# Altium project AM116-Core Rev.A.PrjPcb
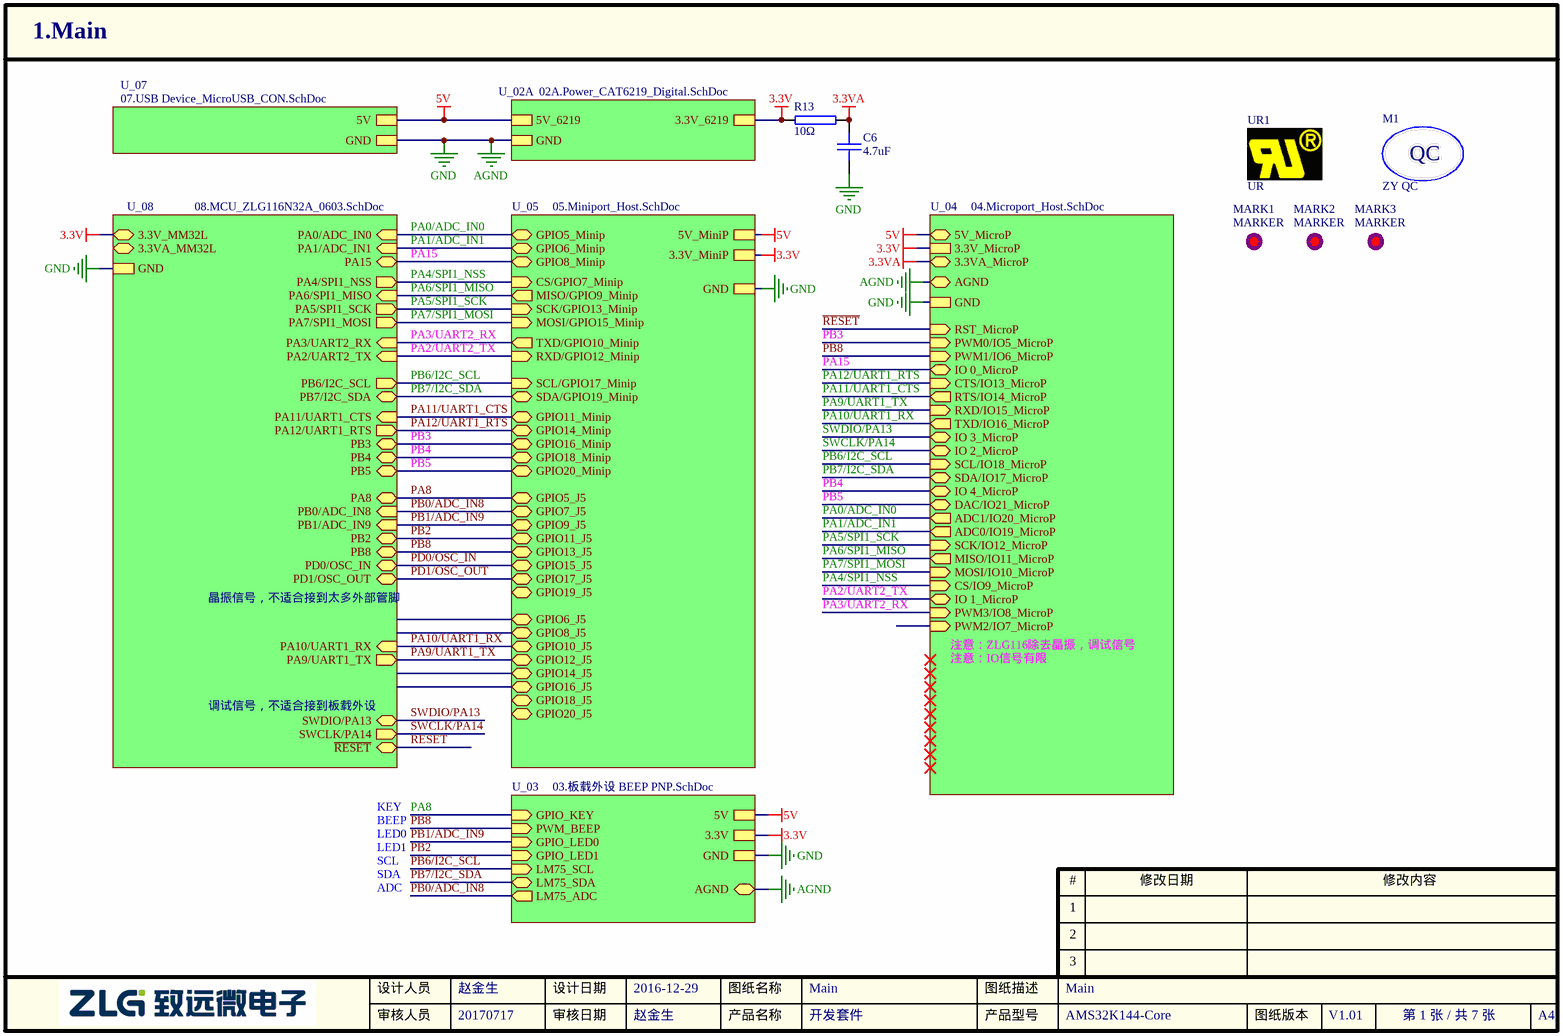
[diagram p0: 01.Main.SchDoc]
7 sheets, 70 parts. Net scope: hierarchical (ports join the sheet entries above them; power ports are global).
Board files: AM116-Core Rev.A.PcbDoc, P-AM116-CORE Rev.A.PcbDoc
Sheets:
  01.Main.SchDoc
    U_02A = 02A.Power_CAT6219_Digital.SchDoc
    U_07 = 07.USB Device_MicroUSB_CON.SchDoc
    U_05 = 05.Miniport_Host.SchDoc
    U_04 = 04.Microport_Host.SchDoc
    U_03 = 03.板载外设 BEEP PNP.SchDoc
    U_08 = 08.MCU_ZLG116N32A_0603.SchDoc

## Sheet 01.Main.SchDoc
size A4; CheckedBy: 20170717; Author: 赵金生; CompanyName: 广州周立功单片机科技有限公司; DocumentNumber: 1; SheetNumber: 1; SheetTotal: 7; PageSetup: Record=PageOptions|CenterHorizontal=True|CenterVertical=True|PrintScale=1.00|XCorrection=1.00|YCorrection=1.00|PrintKind=0|BorderSize=5000000|LeftOffset=0|BottomOffset=0|Orientation=2|PaperLength=1000|PaperWidth=1000|Scale=100|PaperSource=7|PrintQuality=600|MediaType=1|DitherType=10|PaperKind=A4|PrintScaleMode=1; DesignDate: 2016-12-29; CheckDate: 赵金生; SheetName: Main; SheetVersion: V1.01; SheetDescription: Main; productModel: AMS32K144-Core; productName: 开发套件

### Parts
C6  4.7uF  [0603C]
M1  ZY QC  [ZY_QC]  (no BOM)
MARK1  MARKER  [MARKER-C-1.0M]  (no BOM)
MARK2  MARKER  [MARKER-C-1.0M]  (no BOM)
MARK3  MARKER  [MARKER-C-1.0M]  (no BOM)
R13  10Ω  [0603R]
UR1  UR  [ZY_UR-3X2]  (no BOM)

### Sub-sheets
U_02A = 02A.Power_CAT6219_Digital.SchDoc: GND, 3.3V_6219, 5V_6219
U_03 = 03.板载外设 BEEP PNP.SchDoc: GND, 3.3V, PWM_BEEP (in), GPIO_LED0 (in), GPIO_LED1 (in), LM75_ADC (out), 5V, LM75_SCL (in), LM75_SDA (bidir), GPIO_KEY (in), AGND
U_04 = 04.Microport_Host.SchDoc: GND, 3.3V_MicroP, RXD/IO15_MicroP (in), TXD/IO16_MicroP (out), AGND, CTS/IO13_MicroP (in), MOSI/IO10_MicroP (in), SCK/IO12_MicroP (in), MISO/IO11_MicroP (out), IO 1_MicroP (bidir), IO 0_MicroP (bidir), IO 3_MicroP (bidir), IO 2_MicroP (bidir), IO 4_MicroP (bidir), PWM1/IO6_MicroP (in), PWM0/IO5_MicroP (in), PWM3/IO8_MicroP (in), PWM2/IO7_MicroP (in), SDA/IO17_MicroP (bidir), SCL/IO18_MicroP (in), ADC1/IO20_MicroP (out), ADC0/IO19_MicroP (out), DAC/IO21_MicroP (bidir), RST_MicroP (in), CS/IO9_MicroP (in), RTS/IO14_MicroP (out), 5V_MicroP, 3.3VA_MicroP
U_05 = 05.Miniport_Host.SchDoc: GND, 3.3V_MiniP, 5V_MiniP, MISO/GPIO9_Minip (out), GPIO5_Minip (bidir), GPIO8_Minip (bidir), SDA/GPIO19_Minip (bidir), SCL/GPIO17_Minip (in), GPIO16_Minip (bidir), GPIO18_Minip (bidir), MOSI/GPIO15_Minip (in), SCK/GPIO13_Minip (in), GPIO11_Minip (bidir), CS/GPIO7_Minip (in), GPIO20_Minip (bidir), GPIO14_Minip (bidir), GPIO6_Minip (bidir), RXD/GPIO12_Minip (in), TXD/GPIO10_Minip (out), GPIO5_J5 (bidir), GPIO6_J5 (bidir), GPIO8_J5 (bidir), GPIO11_J5 (bidir), GPIO14_J5 (bidir), GPIO16_J5 (bidir), GPIO18_J5 (bidir), GPIO20_J5 (bidir), GPIO9_J5 (bidir), GPIO10_J5 (bidir), GPIO12_J5 (bidir), GPIO7_J5 (bidir), GPIO13_J5 (bidir), GPIO15_J5 (bidir), GPIO17_J5 (bidir), GPIO19_J5 (bidir)
U_07 = 07.USB Device_MicroUSB_CON.SchDoc: 5V, GND
U_08 = 08.MCU_ZLG116N32A_0603.SchDoc: GND, PA15 (bidir), 3.3V_MM32L, SWCLK/PA14 (out), PB4 (bidir), PB3 (bidir), PA4/SPI1_NSS (out), PA0/ADC_IN0 (in), PA8 (bidir), PB2 (bidir), PA10/UART1_RX (in), PA1/ADC_IN1 (in), PB6/I2C_SCL (out), PB5 (bidir), PA11/UART1_CTS (in), PB7/I2C_SDA (bidir), PA6/SPI1_MISO (in), PA7/SPI1_MOSI (out), PB0/ADC_IN8 (in), PB1/ADC_IN9 (in), SWDIO/PA13 (bidir), PA12/UART1_RTS (out), PA9/UART1_TX (out), PA2/UART2_TX (in), PA3/UART2_RX (in), PA5/SPI1_SCK (out), PB8 (bidir), PD0/OSC_IN (bidir), PD1/OSC_OUT (bidir), ~{RESET} (bidir), 3.3VA_MM32L

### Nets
3.3V: R13.2 ; sheet U_02A/3.3V_6219, sheet U_05/3.3V_MiniP, sheet U_04/3.3V_MicroP, sheet U_03/3.3V, sheet U_08/3.3V_MM32L
3.3VA: C6.2 R13.1 ; sheet U_04/3.3VA_MicroP
5V: sheet U_02A/5V_6219, sheet U_07/5V, sheet U_05/5V_MiniP, sheet U_04/5V_MicroP, sheet U_03/5V
AGND: C6.1 ; sheet U_02A/GND, sheet U_07/GND, sheet U_05/GND, sheet U_04/GND, sheet U_04/AGND, sheet U_03/GND, sheet U_03/AGND, sheet U_08/GND  [also labelled GND]
PA0/ADC_IN0: sheet U_05/GPIO5_Minip, sheet U_04/ADC1/IO20_MicroP, sheet U_08/PA0/ADC_IN0  [project net ADC1/IO20_MicroP]
PA1/ADC_IN1: sheet U_05/GPIO6_Minip, sheet U_04/ADC0/IO19_MicroP, sheet U_08/PA1/ADC_IN1  [project net ADC0/IO19_MicroP]
PA2/UART2_TX: sheet U_05/RXD/GPIO12_Minip, sheet U_04/IO 1_MicroP, sheet U_08/PA2/UART2_TX  [project net IO 1_MicroP]
PA3/UART2_RX: sheet U_05/TXD/GPIO10_Minip, sheet U_04/PWM3/IO8_MicroP, sheet U_08/PA3/UART2_RX
PA4/SPI1_NSS: sheet U_05/CS/GPIO7_Minip, sheet U_04/CS/IO9_MicroP, sheet U_08/PA4/SPI1_NSS  [project net CS/GPIO7_Minip]
PA5/SPI1_SCK: sheet U_05/SCK/GPIO13_Minip, sheet U_04/SCK/IO12_MicroP, sheet U_08/PA5/SPI1_SCK
PA6/SPI1_MISO: sheet U_05/MISO/GPIO9_Minip, sheet U_04/MISO/IO11_MicroP, sheet U_08/PA6/SPI1_MISO  [project net MISO/GPIO9_Minip]
PA7/SPI1_MOSI: sheet U_05/MOSI/GPIO15_Minip, sheet U_04/MOSI/IO10_MicroP, sheet U_08/PA7/SPI1_MOSI  [project net MOSI/GPIO15_Minip]
PA8: sheet U_05/GPIO5_J5, sheet U_03/GPIO_KEY, sheet U_08/PA8  [project net GPIO5_J5]
PA9/UART1_TX: sheet U_05/GPIO12_J5, sheet U_04/RXD/IO15_MicroP, sheet U_08/PA9/UART1_TX  [project net GPIO12_J5]
PA10/UART1_RX: sheet U_05/GPIO10_J5, sheet U_04/TXD/IO16_MicroP, sheet U_08/PA10/UART1_RX  [project net GPIO10_J5]
PA11/UART1_CTS: sheet U_05/GPIO11_Minip, sheet U_04/RTS/IO14_MicroP, sheet U_08/PA11/UART1_CTS  [project net GPIO11_Minip]
PA12/UART1_RTS: sheet U_05/GPIO14_Minip, sheet U_04/CTS/IO13_MicroP, sheet U_08/PA12/UART1_RTS  [project net CTS/IO13_MicroP]
PA15: sheet U_05/GPIO8_Minip, sheet U_04/IO 0_MicroP, sheet U_08/PA15  [project net GPIO8_Minip]
PB0/ADC_IN8: sheet U_05/GPIO7_J5, sheet U_03/LM75_ADC, sheet U_08/PB0/ADC_IN8  [project net GPIO7_J5]
PB1/ADC_IN9: sheet U_05/GPIO9_J5, sheet U_03/GPIO_LED0, sheet U_08/PB1/ADC_IN9  [project net GPIO9_J5]
PB2: sheet U_05/GPIO11_J5, sheet U_03/GPIO_LED1, sheet U_08/PB2  [project net GPIO11_J5]
PB3: sheet U_05/GPIO16_Minip, sheet U_04/PWM0/IO5_MicroP, sheet U_08/PB3  [project net GPIO16_Minip]
PB4: sheet U_05/GPIO18_Minip, sheet U_04/IO 4_MicroP, sheet U_08/PB4  [project net GPIO18_Minip]
PB5: sheet U_05/GPIO20_Minip, sheet U_04/DAC/IO21_MicroP, sheet U_08/PB5  [project net DAC/IO21_MicroP]
PB6/I2C_SCL: sheet U_05/SCL/GPIO17_Minip, sheet U_04/SCL/IO18_MicroP, sheet U_03/LM75_SCL, sheet U_08/PB6/I2C_SCL  [project net LM75_SCL]
PB7/I2C_SDA: sheet U_05/SDA/GPIO19_Minip, sheet U_04/SDA/IO17_MicroP, sheet U_03/LM75_SDA, sheet U_08/PB7/I2C_SDA  [project net LM75_SDA]
PB8: sheet U_05/GPIO13_J5, sheet U_04/PWM1/IO6_MicroP, sheet U_03/PWM_BEEP, sheet U_08/PB8  [project net GPIO13_J5]
PD0/OSC_IN: sheet U_05/GPIO15_J5, sheet U_08/PD0/OSC_IN  [project net GPIO15_J5]
PD1/OSC_OUT: sheet U_05/GPIO17_J5, sheet U_08/PD1/OSC_OUT  [project net GPIO17_J5]
~{RESET}: sheet U_04/RST_MicroP, sheet U_08/~{RESET}
SWCLK/PA14: sheet U_04/IO 2_MicroP, sheet U_08/SWCLK/PA14  [project net IO 2_MicroP]
SWDIO/PA13: sheet U_04/IO 3_MicroP, sheet U_08/SWDIO/PA13  [project net IO 3_MicroP]

Not connected (* = marked no-connect by the designer): MARK1 0; MARK2 0; MARK3 0

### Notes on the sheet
- 晶振信号，不适合接到太多外部管脚
- 注意：ZLG116除去晶振，调试信号
- 调试信号，不适合接到板载外设
- 注意：IO信号有限
- BEEP
- LED0
- LED1
- KEY
- SCL
- SDA
- ADC

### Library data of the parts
C6 = 1.02.01.0080: GRM188R61A475KE15D,4.7uF,±10%,10V,X5R,0603,muRata,RoHS; 名称: 电容; 封装: 0603; 贴片和直插: SMT; PCB备注: 160602yjh; 器件优选方案: 正常状态，可以选用
R13 = 1.01.01.0007: 10Ω,0603,*,RoHS; 名称: 电阻; 封装: 0603; 设备封装名称: R0603_10R; 厂商: Ralec; 贴片和直插: SMT; 器件优选方案: 正常状态，可以选用

## Sheet 02A.Power_CAT6219_Digital.SchDoc
size A4; CompanyName: 广州周立功单片机科技有限公司; DocumentNumber: 2; SheetNumber: 2; SheetTotal: 7; PageSetup: Record=PageOptions|CenterHorizontal=True|CenterVertical=True|PrintScale=1.00|XCorrection=1.00|YCorrection=1.00|PrintKind=0|BorderSize=5000000|LeftOffset=0|BottomOffset=0|Orientation=2|PaperLength=1000|PaperWidth=1000|Scale=100|PaperSource=7|PrintQuality=600|MediaType=1|DitherType=10|PaperKind=A4|PrintScaleMode=1; DesignDate: 20170717; CheckDate: 20170717; SheetName: POWER_CAT6219; SheetVersion: V1.00; SheetDescription: 基于CAT6219的数字电源电路
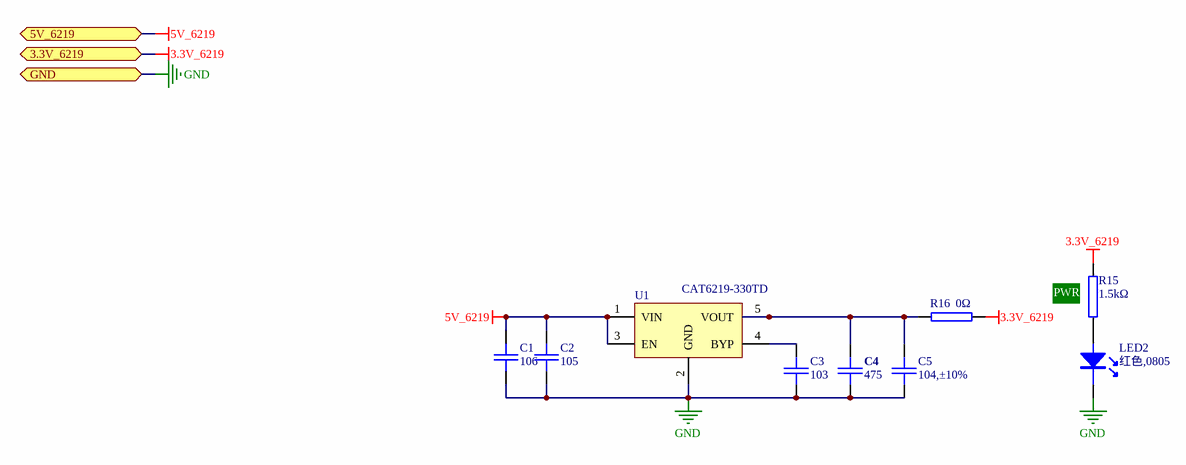
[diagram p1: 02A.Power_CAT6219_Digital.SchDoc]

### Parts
C1  106  [0805C]
C2  105  [0603C]
C3  103  [0603C]
C4  475  [0805C]
C5  104,±10%  [0603C]
LED2  value 红色,0805  [LED-0805]  (hidden comment: LED1)
R15  1.5kΩ  [0603R]
R16  0Ω  [0603R]
U1  CAT6219-330TD  [SOT-23-5]

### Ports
3.3V_6219, 5V_6219, GND

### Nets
3.3V_6219: R15.1 R16.2 ; port 3.3V_6219  [project net 3.3V]
5V_6219: C1.1 C2.1 U1.1(VIN) U1.3(EN) ; port 5V_6219  [project net 5V]
GND: C1.2 C2.2 C3.2 C4.2 C5.2 LED2.2 U1.2(GND) ; port GND  [project net AGND]
NetC3_1: C3.1 U1.4(BYP)
NetC4_1: C4.1 C5.1 R16.1 U1.5(VOUT)
NetLED2_1: LED2.1 R15.2

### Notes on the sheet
- (near R15) PWR

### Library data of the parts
C1 = 1.02.02.0055: 106,10μF,±10%,10V,X5R,0805,RoHS; 名称: 电容; 封装: 0805; 贴片和直插: SMT; 器件优选方案: 量产物料,优先选用; 设备封装名称: C0805_106_X5R_10V_10%
C2 = 1.02.01.0036: 105,1μF,±10%,16V,X7R,0603,*,RoHS; 名称: 电容; 封装: 0603; 设备封装名称: C0603_105_X7R_16V_10%; 厂商: TDK; 贴片和直插: SMT; 器件优选方案: 量产物料,不推荐使用
C3 = 1.02.01.0024: 103,±10%,50V,X7R,0603,*,RoHS; 名称: 电容; 封装: 0603; 设备封装名称: C0603_103_X7R_50V_10%; 厂商: muRata; 贴片和直插: SMT; 器件优选方案: 量产物料,不推荐使用
C4 = 1.02.02.0064: 475,±10%,16V,X7R,0805,RoHS; 名称: 电容; 封装: 0805; 设备封装名称: C0805_475_X7R_16V_10%; 贴片和直插: SMT; 器件优选方案: 优先选用
C5 = 1.02.01.0032: Capacitor; 名称: 电容; 封装: 0603; 设备封装名称: C0603_104_X7R_50V_10%; 厂商: muRata; 型号: 104,±10%,50V,X7R; 贴片和直插: SMT; 器件优选方案: 量产物料,优先选用
LED2 = 1.04.05.0001: 红色,0805,0805,RoHS; 名称: 发光二极管; 封装: 0805; 设备封装名称: LED0805-RED; 贴片和直插: SMT; 器件优选方案: 样品物料,谨慎选用
R15 = 1.01.01.0037: 1.5KΩ,0603,*,RoHS; 名称: 电阻; 封装: 0603; 设备封装名称: R0603_1.5K; 厂商: Ralec; 贴片和直插: SMT; 器件优选方案: 状态正常
R16 = 1.01.01.0001: 名称: 电阻; 封装: 0603; 设备封装名称: R0603_0R; 厂商: Ralec; 贴片和直插: SMT; 器件优选方案: 状态正常
U1 = 1.05.10.0321: CAT6219-330TD,TSOT-23-5,ON,RoHS; 名称: 集成电路; 设备封装名称: TSOT-23-5_CAT6219-330TD-GT3; 贴片和直插: SMT; 器件优选方案: 量产物料,优先选用

## Sheet 07.USB Device_MicroUSB_CON.SchDoc
size A4; CheckedBy: 20170717; Author: 赵金生; CompanyName: 广州周立功单片机科技有限公司; DocumentNumber: 6; SheetNumber: 6; SheetTotal: 7; PageSetup: Record=PageOptions|CenterHorizontal=True|CenterVertical=True|PrintScale=1.00|XCorrection=1.00|YCorrection=1.00|PrintKind=0|BorderSize=5000000|LeftOffset=0|BottomOffset=0|Orientation=2|PaperLength=1000|PaperWidth=1000|Scale=100|PaperSource=7|PrintQuality=600|MediaType=1|DitherType=10|PaperKind=A4|PrintScaleMode=1; DesignDate: 20170717; CheckDate: 赵金生; SheetName: USB接口电路; SheetVersion: <图纸版本>; SheetDescription: USB接口电路，纯供电，没有usb信号
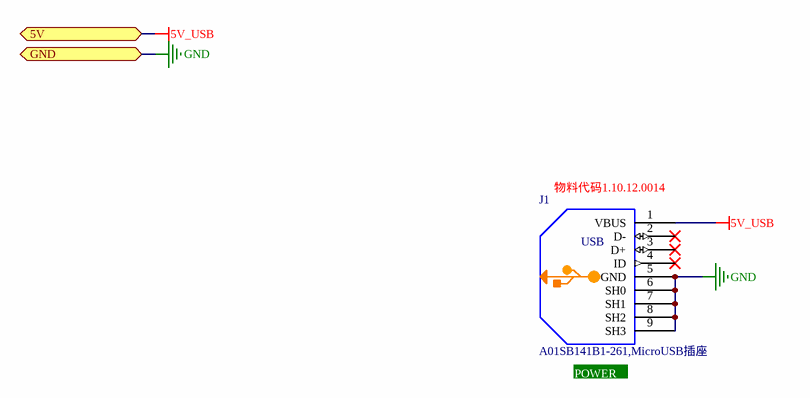
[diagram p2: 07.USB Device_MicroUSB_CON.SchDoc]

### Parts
J1  A01SB141B1-261,MicroUSB插座  [MICROUSB-5S]

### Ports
5V, GND

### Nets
5V_USB: J1.1(VBUS) ; port 5V  [project net 5V]
GND: J1.5(GND) J1.6(SH0) J1.7(SH1) J1.8(SH2) J1.9(SH3) ; port GND  [project net AGND]

Not connected (* = marked no-connect by the designer): J1 2(D-)* 3(D+)* 4(ID)*

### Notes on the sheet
- (near J1) 物料代码1.10.12.0014
- (near J1) POWER

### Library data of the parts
J1 = 1.10.12.0014: A01SB141B1-261,MicroUSB插座,SMT,艾立信,RoHS; PCB备注: 141030lmd; 器件优选方案: 正常状态，可以选用

## Sheet 05.Miniport_Host.SchDoc
size A4; CheckedBy: <审核日期>; Author: 黄雄波; CompanyName: 广州周立功单片机科技有限公司; DocumentNumber: 5; SheetNumber: 5; SheetTotal: 7; PageSetup: Record=PageOptions|CenterHorizontal=True|CenterVertical=True|PrintScale=1.00|XCorrection=1.00|YCorrection=1.00|PrintKind=0|BorderSize=5000000|LeftOffset=0|BottomOffset=0|Orientation=2|PaperLength=1000|PaperWidth=1000|Scale=100|PaperSource=7|PrintQuality=600|MediaType=1|DitherType=10|PaperKind=A4|PrintScaleMode=1; DesignDate: 2016-12-27; CheckDate: <审核人员>; SheetName: MiniPort接口; SheetVersion: V1.01; SheetDescription: MiniPort接口; productModel: AM116-Core; productName: 开发套件
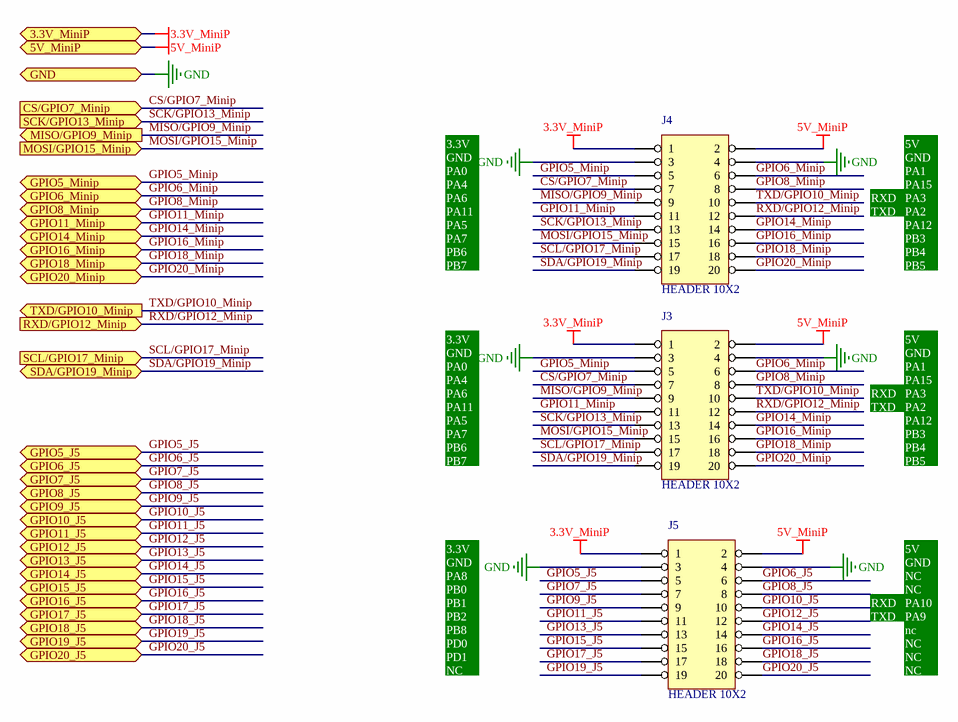
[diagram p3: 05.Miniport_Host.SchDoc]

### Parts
J3  HEADER 10X2  [IDC-20-2.54-R90]
J4  HEADER 10X2  [IDC-20-2.54-R90]
J5  HEADER 10X2  [IDC-20-2.54-R90]

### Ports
3.3V_MiniP, 5V_MiniP, CS/GPIO7_Minip (in), GND, GPIO5_J5 (bidir), GPIO5_Minip (bidir), GPIO6_J5 (bidir), GPIO6_Minip (bidir), GPIO7_J5 (bidir), GPIO8_J5 (bidir), GPIO8_Minip (bidir), GPIO9_J5 (bidir), GPIO10_J5 (bidir), GPIO11_J5 (bidir), GPIO11_Minip (bidir), GPIO12_J5 (bidir), GPIO13_J5 (bidir), GPIO14_J5 (bidir), GPIO14_Minip (bidir), GPIO15_J5 (bidir), GPIO16_J5 (bidir), GPIO16_Minip (bidir), GPIO17_J5 (bidir), GPIO18_J5 (bidir), GPIO18_Minip (bidir), GPIO19_J5 (bidir), GPIO20_J5 (bidir), GPIO20_Minip (bidir), MISO/GPIO9_Minip (out), MOSI/GPIO15_Minip (in), RXD/GPIO12_Minip (in), SCK/GPIO13_Minip (in), SCL/GPIO17_Minip (in), SDA/GPIO19_Minip (bidir), TXD/GPIO10_Minip (out)

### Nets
3.3V_MiniP: J3.1 J4.1 J5.1 ; port 3.3V_MiniP  [project net 3.3V]
5V_MiniP: J3.2 J4.2 J5.2 ; port 5V_MiniP  [project net 5V]
GND: J3.3 J3.4 J4.3 J4.4 J5.3 J5.4 ; port GND  [project net AGND]
CS/GPIO7_Minip: J3.7 J4.7 ; port CS/GPIO7_Minip
GPIO5_J5: J5.5 ; port GPIO5_J5
GPIO5_Minip: J3.5 J4.5 ; port GPIO5_Minip  [project net ADC1/IO20_MicroP]
GPIO6_J5: J5.6 ; port GPIO6_J5
GPIO6_Minip: J3.6 J4.6 ; port GPIO6_Minip  [project net ADC0/IO19_MicroP]
GPIO7_J5: J5.7 ; port GPIO7_J5
GPIO8_J5: J5.8 ; port GPIO8_J5
GPIO8_Minip: J3.8 J4.8 ; port GPIO8_Minip
GPIO9_J5: J5.9 ; port GPIO9_J5
GPIO10_J5: J5.10 ; port GPIO10_J5
GPIO11_J5: J5.11 ; port GPIO11_J5
GPIO11_Minip: J3.11 J4.11 ; port GPIO11_Minip
GPIO12_J5: J5.12 ; port GPIO12_J5
GPIO13_J5: J5.13 ; port GPIO13_J5
GPIO14_J5: J5.14 ; port GPIO14_J5
GPIO14_Minip: J3.14 J4.14 ; port GPIO14_Minip  [project net CTS/IO13_MicroP]
GPIO15_J5: J5.15 ; port GPIO15_J5
GPIO16_J5: J5.16 ; port GPIO16_J5
GPIO16_Minip: J3.16 J4.16 ; port GPIO16_Minip
GPIO17_J5: J5.17 ; port GPIO17_J5
GPIO18_J5: J5.18 ; port GPIO18_J5
GPIO18_Minip: J3.18 J4.18 ; port GPIO18_Minip
GPIO19_J5: J5.19 ; port GPIO19_J5
GPIO20_J5: J5.20 ; port GPIO20_J5
GPIO20_Minip: J3.20 J4.20 ; port GPIO20_Minip  [project net DAC/IO21_MicroP]
MISO/GPIO9_Minip: J3.9 J4.9 ; port MISO/GPIO9_Minip
MOSI/GPIO15_Minip: J3.15 J4.15 ; port MOSI/GPIO15_Minip
RXD/GPIO12_Minip: J3.12 J4.12 ; port RXD/GPIO12_Minip  [project net IO 1_MicroP]
SCK/GPIO13_Minip: J3.13 J4.13 ; port SCK/GPIO13_Minip  [project net PA5/SPI1_SCK]
SCL/GPIO17_Minip: J3.17 J4.17 ; port SCL/GPIO17_Minip  [project net LM75_SCL]
SDA/GPIO19_Minip: J3.19 J4.19 ; port SDA/GPIO19_Minip  [project net LM75_SDA]
TXD/GPIO10_Minip: J3.10 J4.10 ; port TXD/GPIO10_Minip  [project net PA3/UART2_RX]

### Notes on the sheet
- 3.3V
  GND
  PA0
  PA4
  PA6
  PA11
  PA5
  PA7
  PB6
  PB7
- TXD
- RXD
- 5V
  GND
  PA1
  PA15
  PA3
  PA2
  PA12
  PB3
  PB4
  PB5
- 3.3V
  GND
  PA8
  PB0
  PB1
  PB2
  PB8
  PD0
  PD1
  NC
- 5V
  GND
  NC
  NC
  PA10
  PA9
  nc
  NC
  NC
  NC

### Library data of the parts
J5 = HEADER 10X2: 物料代码: 1.10.11.0076

## Sheet 04.Microport_Host.SchDoc
size A4; CheckedBy: <审核日期>; Author: 赵金生; CompanyName: 广州周立功单片机科技有限公司; DocumentNumber: 4; SheetNumber: 4; SheetTotal: 7; PageSetup: Record=PageOptions|CenterHorizontal=True|CenterVertical=True|PrintScale=1.00|XCorrection=1.00|YCorrection=1.00|PrintKind=0|BorderSize=5000000|LeftOffset=0|BottomOffset=0|Orientation=2|PaperLength=1000|PaperWidth=1000|Scale=100|PaperSource=7|PrintQuality=600|MediaType=1|DitherType=10|PaperKind=A4|PrintScaleMode=1; DesignDate: 2016-12-29; CheckDate: <审核人员>; SheetName: MicroPort接口; SheetVersion: V1.01; SheetDescription: MicroPort接口; productModel: AM116-Core; productName: 开发套件
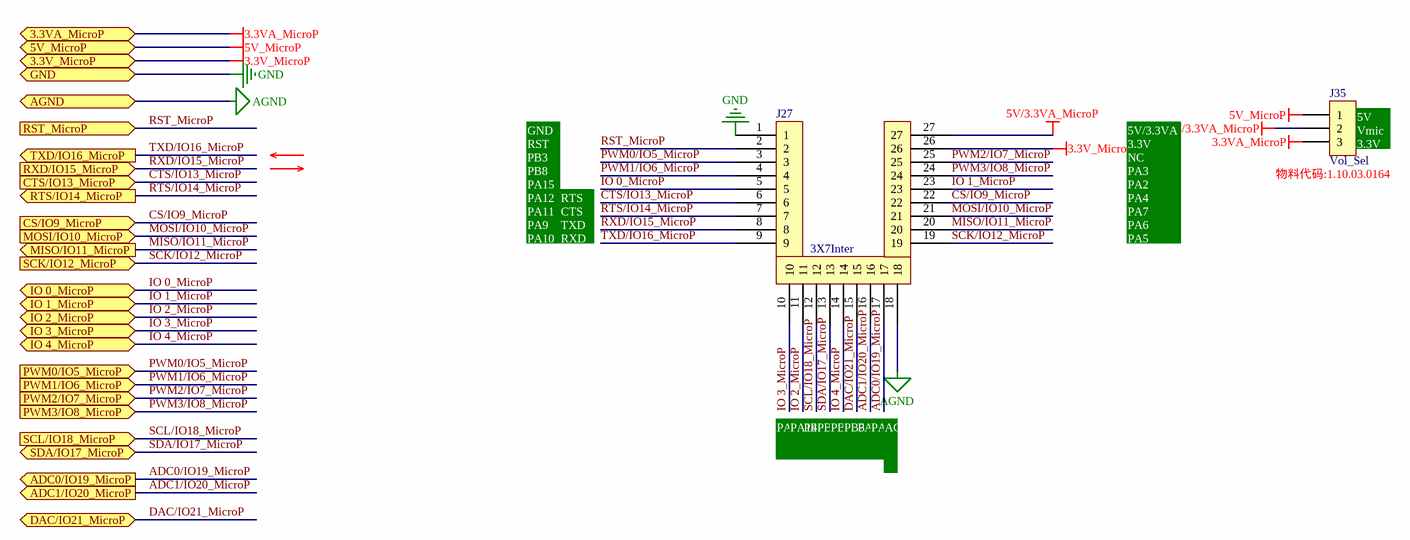
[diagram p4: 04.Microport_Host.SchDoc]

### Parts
J27  3X7Inter  [SIP-27 2.54C]
J35  Vol_Sel  [SIP-3-2.54]

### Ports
3.3V_MicroP, 3.3VA_MicroP, 5V_MicroP, ADC0/IO19_MicroP (out), ADC1/IO20_MicroP (out), AGND, CS/IO9_MicroP (in), CTS/IO13_MicroP (in), DAC/IO21_MicroP (bidir), GND, IO 0_MicroP (bidir), IO 1_MicroP (bidir), IO 2_MicroP (bidir), IO 3_MicroP (bidir), IO 4_MicroP (bidir), MISO/IO11_MicroP (out), MOSI/IO10_MicroP (in), PWM0/IO5_MicroP (in), PWM1/IO6_MicroP (in), PWM2/IO7_MicroP (in), PWM3/IO8_MicroP (in), RST_MicroP (in), RTS/IO14_MicroP (out), RXD/IO15_MicroP (in), SCK/IO12_MicroP (in), SCL/IO18_MicroP (in), SDA/IO17_MicroP (bidir), TXD/IO16_MicroP (out)

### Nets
3.3V_MicroP: J27.26 ; port 3.3V_MicroP  [project net 3.3V]
3.3VA_MicroP: J35.3 ; port 3.3VA_MicroP  [project net 3.3VA]
5V/3.3VA_MicroP: J27.27 J35.2
5V_MicroP: J35.1 ; port 5V_MicroP  [project net 5V]
AGND: J27.1 J27.18 ; port GND, port AGND  [also labelled GND]
ADC0/IO19_MicroP: J27.17 ; port ADC0/IO19_MicroP
ADC1/IO20_MicroP: J27.16 ; port ADC1/IO20_MicroP
CS/IO9_MicroP: J27.22 ; port CS/IO9_MicroP  [project net CS/GPIO7_Minip]
CTS/IO13_MicroP: J27.6 ; port CTS/IO13_MicroP
DAC/IO21_MicroP: J27.15 ; port DAC/IO21_MicroP
IO 0_MicroP: J27.5 ; port IO 0_MicroP  [project net GPIO8_Minip]
IO 1_MicroP: J27.23 ; port IO 1_MicroP
IO 2_MicroP: J27.11 ; port IO 2_MicroP
IO 3_MicroP: J27.10 ; port IO 3_MicroP
IO 4_MicroP: J27.14 ; port IO 4_MicroP  [project net GPIO18_Minip]
MISO/IO11_MicroP: J27.20 ; port MISO/IO11_MicroP  [project net MISO/GPIO9_Minip]
MOSI/IO10_MicroP: J27.21 ; port MOSI/IO10_MicroP  [project net MOSI/GPIO15_Minip]
PWM0/IO5_MicroP: J27.3 ; port PWM0/IO5_MicroP  [project net GPIO16_Minip]
PWM1/IO6_MicroP: J27.4 ; port PWM1/IO6_MicroP  [project net GPIO13_J5]
PWM2/IO7_MicroP: J27.25 ; port PWM2/IO7_MicroP
PWM3/IO8_MicroP: J27.24 ; port PWM3/IO8_MicroP  [project net PA3/UART2_RX]
RST_MicroP: J27.2 ; port RST_MicroP  [project net ~{RESET}]
RTS/IO14_MicroP: J27.7 ; port RTS/IO14_MicroP  [project net GPIO11_Minip]
RXD/IO15_MicroP: J27.8 ; port RXD/IO15_MicroP  [project net GPIO12_J5]
SCK/IO12_MicroP: J27.19 ; port SCK/IO12_MicroP  [project net PA5/SPI1_SCK]
SCL/IO18_MicroP: J27.12 ; port SCL/IO18_MicroP  [project net LM75_SCL]
SDA/IO17_MicroP: J27.13 ; port SDA/IO17_MicroP  [project net LM75_SDA]
TXD/IO16_MicroP: J27.9 ; port TXD/IO16_MicroP  [project net GPIO10_J5]

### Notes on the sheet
- (near J35) 物料代码:1.10.03.0164
- (near J35) 5V
- (near J35) Vmic
  3.3V
- GND
  RST
  PB3
  PB8
  PA15
  PA12
  PA11
  PA9
  PA10
- TXD
- RXD
- RTS
- CTS
- 5V/3.3VA
  3.3V
  NC
  PA3
  PA2
  PA4
  PA7
  PA6
  PA5
- PA13
- PA14
- PB6
- PB7
- PB4
- PB5
- PA0
- PA1
- AGND

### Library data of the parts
J27 = 3X7Inter: 物料代码: 1.10.11.0074
J35 = CON3: Connector; 物料代码: 1.10.03.0164

## Sheet 03.板载外设 BEEP PNP.SchDoc
size A4; CheckedBy: <审核日期>; Author: 黄雄波; CompanyName: 广州周立功单片机科技有限公司; DocumentNumber: 3; SheetNumber: 3; SheetTotal: 7; PageSetup: Record=PageOptions|CenterHorizontal=True|CenterVertical=True|PrintScale=1.00|XCorrection=1.00|YCorrection=1.00|PrintKind=0|BorderSize=5000000|LeftOffset=0|BottomOffset=0|Orientation=2|PaperLength=1000|PaperWidth=1000|Scale=100|PaperSource=7|PrintQuality=600|MediaType=1|DitherType=10|PaperKind=A4|PrintScaleMode=1; DesignDate: 2016-12-29; CheckDate: <审核人员>; SheetName: 板载外设; SheetVersion: V1.01; SheetDescription: 板载外设; productModel: AM116-Core; productName: 开发套件
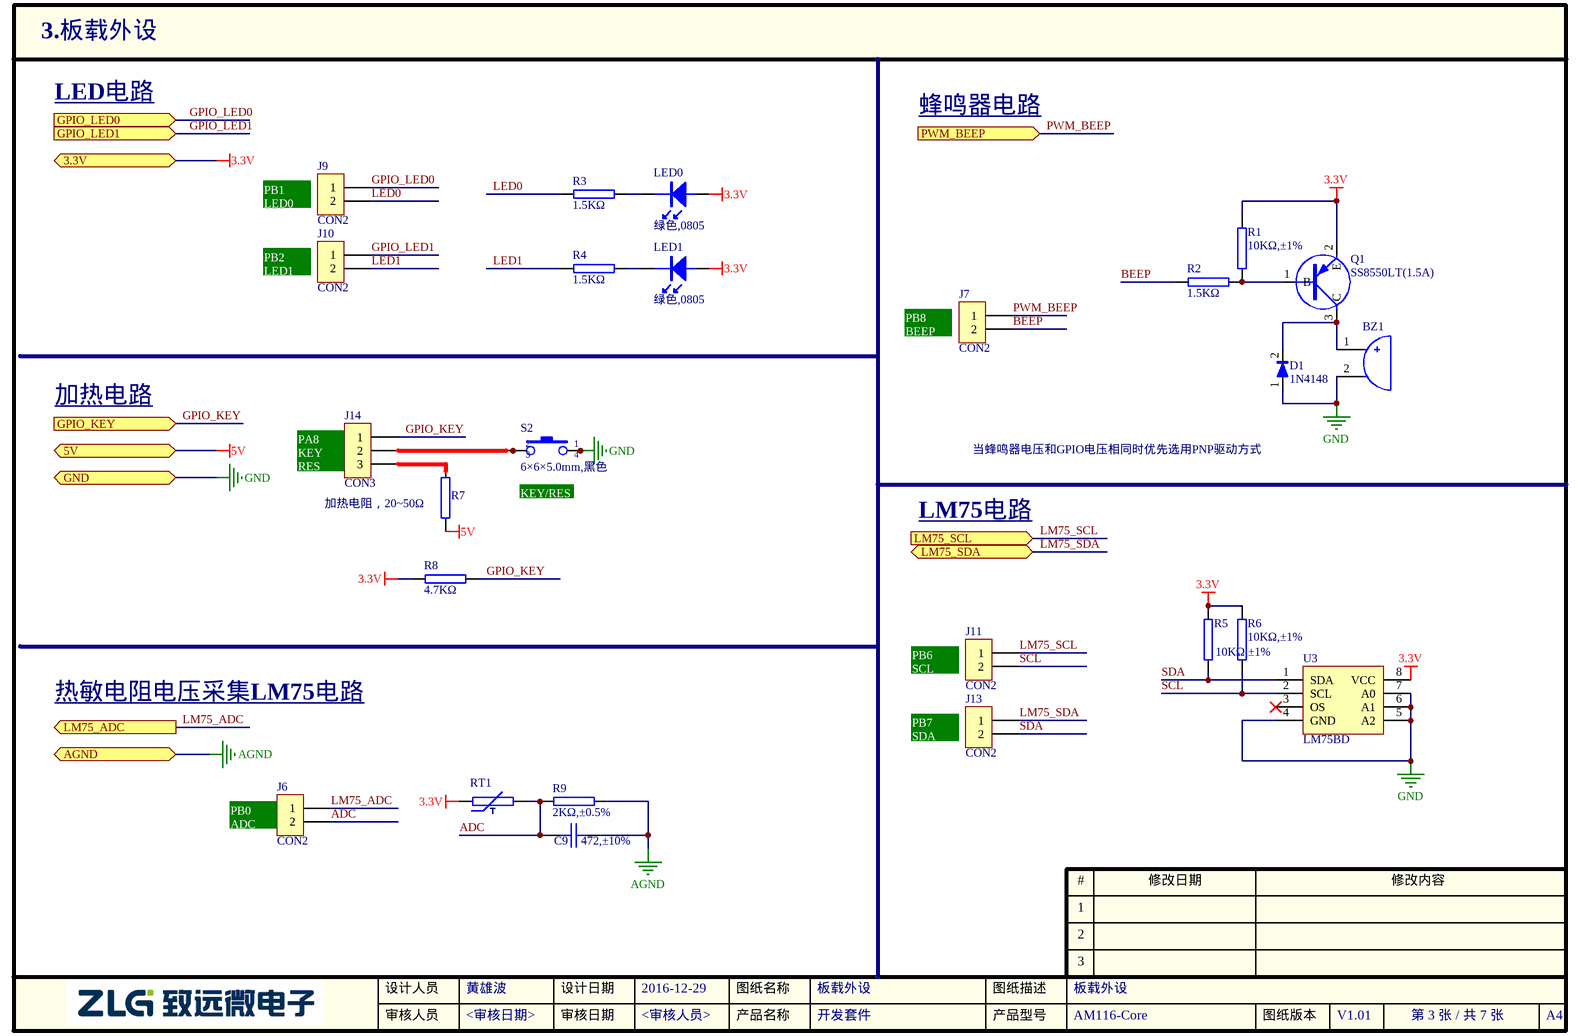
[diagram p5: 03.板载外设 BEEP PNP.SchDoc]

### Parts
BZ1  BUZZER2  [BUZZ-4/9]  (value not drawn)
C9  472,±10%  [0603C]
D1  value 1N4148  [SOD-323]  (hidden comment: DIODE1)
J6  CON2  [SIP-2-2.54]
J7  CON2  [SIP-2-2.54]
J9  CON2  [SIP-2-2.54]
J10  CON2  [SIP-2-2.54]
J11  CON2  [SIP-2-2.54]
J13  CON2  [SIP-2-2.54]
J14  CON3  [SIP-3-2.54]
LED0  value 绿色,0805  [LED-0805]  (hidden comment: LED1)
LED1  value 绿色,0805  [LED-0805]  (hidden comment: LED1)
Q1  value SS8550LT(1.5A)  [SOT-23]  (hidden comment: PNP-1)
R1  10KΩ,±1%  [0603R]
R2  1.5KΩ  [0603R]
R3  1.5KΩ  [0603R]
R4  1.5KΩ  [0603R]
R5  10KΩ,±1%  [0603R]
R6  10KΩ,±1%  [0603R]
R7  20Ω,±5%  [RESAD1778W80L1450D430P]  (value not drawn)
R8  4.7KΩ  [0603R]
R9  2KΩ,±0.5%  [0603R]
RT1  MF52E-103F3435FB-A(2.5MM)  [RES-NTC(2.0)]  (value not drawn)
S2  value 6×6×5.0mm,黑色  [KEY-6S]  (hidden comment: SW-PB4P)
U3  value LM75BD  [SOIC127P600X175-8N]  (hidden comment: LM75B)

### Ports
3.3V, 5V, AGND, GND, GPIO_KEY (in), GPIO_LED0 (in), GPIO_LED1 (in), LM75_ADC (out), LM75_SCL (in), LM75_SDA (bidir), PWM_BEEP (in)

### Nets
3.3V: LED0.1 LED1.1 Q1.2(E) R1.2 R5.2 R6.2 R8.2 RT1.1 U3.8(VCC) ; port 3.3V
5V: R7.1 ; port 5V
AGND: BZ1.2(B) C9.2 D1.1 R9.2 S2.1 S2.4 U3.4(GND) U3.5(A2) U3.6(A1) U3.7(A0) ; port GND, port AGND  [also labelled GND]
ADC: C9.1 J6.2 R9.1 RT1.2
BEEP: J7.2 R2.1
GPIO_KEY: J14.1 R8.1 ; port GPIO_KEY  [project net GPIO5_J5]
GPIO_LED0: J9.1 ; port GPIO_LED0  [project net GPIO9_J5]
GPIO_LED1: J10.1 ; port GPIO_LED1  [project net GPIO11_J5]
LED0: J9.2 R3.2
LED1: J10.2 R4.2
LM75_ADC: J6.1 ; port LM75_ADC  [project net GPIO7_J5]
LM75_SCL: J11.1 ; port LM75_SCL
LM75_SDA: J13.1 ; port LM75_SDA
PWM_BEEP: J7.1 ; port PWM_BEEP  [project net GPIO13_J5]
SCL: J11.2 R6.1 U3.2(SCL)
SDA: J13.2 R5.1 U3.1(SDA)
NetBZ1_1: BZ1.1(A) D1.2 Q1.3(C)
NetJ14_2: J14.2 S2.2 S2.3
NetJ14_3: J14.3 R7.2
NetLED0_2: LED0.2 R3.1
NetLED1_2: LED1.2 R4.1
NetQ1_1: Q1.1(B) R1.1 R2.2

Not connected (* = marked no-connect by the designer): U3 3(OS)*

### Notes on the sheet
- LED电路
- 蜂鸣器电路
- (near J9) PB1
  LED0
- (near J10) PB2
  LED1
- (near J7) PB8
  BEEP
- 加热电路
- (near J14) PA8
  KEY
  RES
- 加热电阻，20~50Ω
- (near S2) KEY/RES
- LM75电路
- 当蜂鸣器电压和GPIO电压相同时优先选用PNP驱动方式
- 热敏电阻电压采集LM75电路
- (near J11) PB6
  SCL
- (near J13) PB7
  SDA
- (near J6) PB0
  ADC

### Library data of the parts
BZ1 = 1.06.09.0016: Buzzer有极性; Value: AS-905I-LF,无源; 名称: 讯响器; 厂商: 常州笠翔; 型号: AS-905I-LF,无源,Ф9×4.8mm; 贴片和直插: THT; PCB备注: Flq-Shcj-Twrj-150113; 器件优选方案: 量产物料,优先选用
C9 = 1.02.01.0057: Capacitor; 名称: 电容; 封装: 0603; 设备封装名称: C0603_820PF_COG_50V_5%; 厂商: muRata; 型号: 472,±10%,50V,X7R; 贴片和直插: SMT; 器件优选方案: 状态正常
D1 = 1.04.07.0027: 1N4148,SOD-323,RoHS; 名称: 二极管; 设备封装名称: SOD-323_1N4148; 贴片和直插: SMT
J6 J7 J9-J11 J13 = CON2: Connector
J14 = CON3: Connector
LED0 LED1 = 1.04.05.0002: 绿色,0805,0805,RoHS; 名称: 发光二极管; 封装: 0805; 设备封装名称: LED0805-GREEN; 贴片和直插: SMT; 器件优选方案: 样品物料,谨慎选用
Q1 = 1.04.09.0002: PNP Transistor; 名称: 三极管; 设备封装名称: SOT-23_SS8550LT; 厂商: 江苏长电; 贴片和直插: SMT
R1 = 1.01.01.0052: 10KΩ,±1%,0603,*,RoHS; 名称: 电阻; 封装: 0603; 设备封装名称: R0603_10K_1%; 厂商: Ralec; 贴片和直插: SMT
R2 = 1.01.01.0037: as R15 on sheet 02A.Power_CAT6219_Digital
R3 R4 = 1.01.01.0037: 1.5KΩ,0603,*,RoHS; 名称: 电阻; 封装: 0603; 设备封装名称: R0603_1.5K; 厂商: Ralec; 贴片和直插: SMT; 器件优选方案: 正常状态，可以选用
R5 R6 = 1.01.01.0052: 10KΩ,±1%,0603,*,RoHS; 名称: 电阻; 封装: 0603; 设备封装名称: R0603_10K_1%; 厂商: Ralec; 贴片和直插: SMT; 器件优选方案: 正常状态，可以选用
R7 = 1.01.10.0003: 20Ω,±5%,2W,Ф5.5×16mm,RoHS; 名称: 电阻; 贴片和直插: THT
R8 = 1.01.01.0045: 4.7KΩ,0603,*,RoHS; 名称: 电阻; 封装: 0603; 设备封装名称: R0603_4.7K; 厂商: Ralec; 贴片和直插: SMT; 器件优选方案: 正常状态，可以选用
R9 = 1.01.01.0084: 名称: 电阻; 封装: 0603; 设备封装名称: R0603_2K_0.5%; 厂商: Ralec; 贴片和直插: SMT
RT1 = 1.01.14.0011: MF52E-103F3435FB-A(2.5MM),THT,RoHS; 名称: 热敏电阻; 器件优选方案: 正常状态，可以选用
S2 = 1.09.01.0003: 6×6×5.0mm,黑色,SMD,,*; 名称: 轻触按键; 贴片和直插: SMT
U3 = 1.05.10.0602: LM75BD,SO-9,NXP,RoHS; 名称: IC; 封装: SO-8; 贴片和直插: SMT; 器件优选方案: 样品物料,谨慎选用

## Sheet 08.MCU_ZLG116N32A_0603.SchDoc
size A4; CheckedBy: <审核日期>; Author: 伍伟业; CompanyName: 广州周立功单片机科技有限公司; DocumentNumber: 7; SheetNumber: 7; SheetTotal: 7; PageSetup: Record=PageOptions|CenterHorizontal=True|CenterVertical=True|PrintScale=1.00|XCorrection=1.00|YCorrection=1.00|PrintKind=0|BorderSize=5000000|LeftOffset=0|BottomOffset=0|Orientation=2|PaperLength=1000|PaperWidth=1000|Scale=100|PaperSource=7|PrintQuality=600|MediaType=1|DitherType=10|PaperKind=A4|PrintScaleMode=1; DesignDate: 2016-8-4; CheckDate: 赵金生; SheetName: MCU_ZLG116N32A; SheetVersion: Rev.A; SheetDescription: ZLG116N32A最小系统
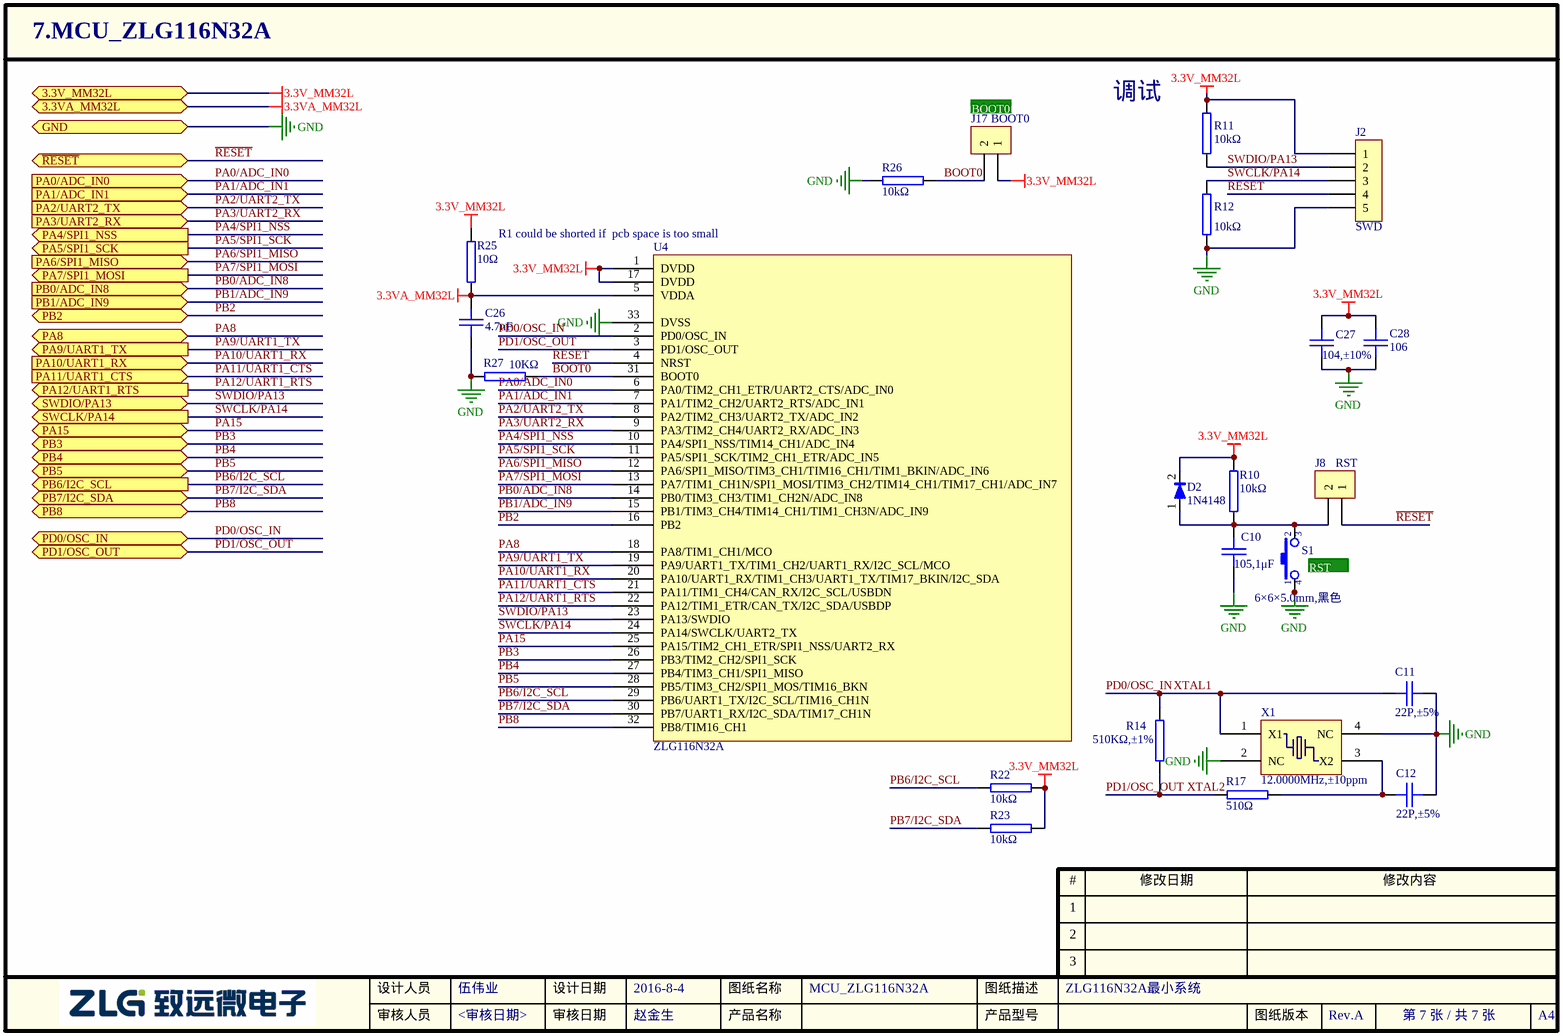
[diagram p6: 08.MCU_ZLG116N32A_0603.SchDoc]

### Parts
C10  105,1μF  [0603C]
C11  22P,±5%  [0603C]
C12  22P,±5%  [0603C]
C26  4.7uF  [0603C]
C27  104,±10%  [0603C]
C28  106  [0805C]
D2  value 1N4148  [SOD-323]  (hidden comment: DIODE1)
J2  SWD  [SIP-5-2.54-R90]
J8  RST  [SIP-2-2.54]
J17  BOOT0  [SIP-2-2.54]
R10  10kΩ  [0603R]
R11  10kΩ  [0603R]
R12  10kΩ  [0603R]
R14  510KΩ,±1%  [禁止选用0603R]
R17  510Ω  [0603R]
R22  10kΩ  [0603R]
R23  10kΩ  [0603R]
R25  10Ω  [0603R]
R26  10kΩ  [0603R]
R27  10KΩ  [0603R]
S1  value 6×6×5.0mm,黑色  [KEY-6S]  (hidden comment: RST)
U4  ZLG116N32A  [QFN50P500X500X85-33N]
X1  12.0000MHz,±10ppm  [XTAL4-3.2X2.5]

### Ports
3.3V_MM32L, 3.3VA_MM32L, GND, PA0/ADC_IN0 (in), PA1/ADC_IN1 (in), PA2/UART2_TX (in), PA3/UART2_RX (in), PA4/SPI1_NSS (out), PA5/SPI1_SCK (out), PA6/SPI1_MISO (in), PA7/SPI1_MOSI (out), PA8 (bidir), PA9/UART1_TX (out), PA10/UART1_RX (in), PA11/UART1_CTS (in), PA12/UART1_RTS (out), PA15 (bidir), PB0/ADC_IN8 (in), PB1/ADC_IN9 (in), PB2 (bidir), PB3 (bidir), PB4 (bidir), PB5 (bidir), PB6/I2C_SCL (out), PB7/I2C_SDA (bidir), PB8 (bidir), PD0/OSC_IN (bidir), PD1/OSC_OUT (bidir), SWCLK/PA14 (out), SWDIO/PA13 (bidir), ~{RESET} (bidir)

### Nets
3.3V_MM32L: C27.1 C28.1 D2.2 J2.1 J17.1 R10.2 R11.2 R22.2 R23.2 R25.2 U4.1(DVDD) U4.17(DVDD) ; port 3.3V_MM32L  [project net 3.3V]
3.3VA_MM32L: C26.1 R25.1 U4.5(VDDA) ; port 3.3VA_MM32L
GND: C10.2 C11.2 C12.2 C26.2 C27.2 C28.2 J2.5 R12.1 R26.1 R27.1 S1.1 S1.4 U4.33(DVSS) X1.2(NC) X1.4(NC) ; port GND  [project net AGND]
BOOT0: J17.2 R26.2 R27.2 U4.31(BOOT0)
PA0/ADC_IN0: U4.6(PA0/TIM2_CH1_ETR/UART2_CTS/ADC_IN0) ; port PA0/ADC_IN0  [project net ADC1/IO20_MicroP]
PA1/ADC_IN1: U4.7(PA1/TIM2_CH2/UART2_RTS/ADC_IN1) ; port PA1/ADC_IN1  [project net ADC0/IO19_MicroP]
PA2/UART2_TX: U4.8(PA2/TIM2_CH3/UART2_TX/ADC_IN2) ; port PA2/UART2_TX  [project net IO 1_MicroP]
PA3/UART2_RX: U4.9(PA3/TIM2_CH4/UART2_RX/ADC_IN3) ; port PA3/UART2_RX
PA4/SPI1_NSS: U4.10(PA4/SPI1_NSS/TIM14_CH1/ADC_IN4) ; port PA4/SPI1_NSS  [project net CS/GPIO7_Minip]
PA5/SPI1_SCK: U4.11(PA5/SPI1_SCK/TIM2_CH1_ETR/ADC_IN5) ; port PA5/SPI1_SCK
PA6/SPI1_MISO: U4.12(PA6/SPI1_MISO/TIM3_CH1/TIM16_CH1/TIM1_BKIN/ADC_IN6) ; port PA6/SPI1_MISO  [project net MISO/GPIO9_Minip]
PA7/SPI1_MOSI: U4.13(PA7/TIM1_CH1N/SPI1_MOSI/TIM3_CH2/TIM14_CH1/TIM17_CH1/ADC_IN7) ; port PA7/SPI1_MOSI  [project net MOSI/GPIO15_Minip]
PA8: U4.18(PA8/TIM1_CH1/MCO) ; port PA8  [project net GPIO5_J5]
PA9/UART1_TX: U4.19(PA9/UART1_TX/TIM1_CH2/UART1_RX/I2C_SCL/MCO) ; port PA9/UART1_TX  [project net GPIO12_J5]
PA10/UART1_RX: U4.20(PA10/UART1_RX/TIM1_CH3/UART1_TX/TIM17_BKIN/I2C_SDA) ; port PA10/UART1_RX  [project net GPIO10_J5]
PA11/UART1_CTS: U4.21(PA11/TIM1_CH4/CAN_RX/I2C_SCL/USBDN) ; port PA11/UART1_CTS  [project net GPIO11_Minip]
PA12/UART1_RTS: U4.22(PA12/TIM1_ETR/CAN_TX/I2C_SDA/USBDP) ; port PA12/UART1_RTS  [project net CTS/IO13_MicroP]
PA15: U4.25(PA15/TIM2_CH1_ETR/SPI1_NSS/UART2_RX) ; port PA15  [project net GPIO8_Minip]
PB0/ADC_IN8: U4.14(PB0/TIM3_CH3/TIM1_CH2N/ADC_IN8) ; port PB0/ADC_IN8  [project net GPIO7_J5]
PB1/ADC_IN9: U4.15(PB1/TIM3_CH4/TIM14_CH1/TIM1_CH3N/ADC_IN9) ; port PB1/ADC_IN9  [project net GPIO9_J5]
PB2: U4.16(PB2) ; port PB2  [project net GPIO11_J5]
PB3: U4.26(PB3/TIM2_CH2/SPI1_SCK) ; port PB3  [project net GPIO16_Minip]
PB4: U4.27(PB4/TIM3_CH1/SPI1_MISO) ; port PB4  [project net GPIO18_Minip]
PB5: U4.28(PB5/TIM3_CH2/SPI1_MOS/TIM16_BKN) ; port PB5  [project net DAC/IO21_MicroP]
PB6/I2C_SCL: R22.1 U4.29(PB6/UART1_TX/I2C_SCL/TIM16_CH1N) ; port PB6/I2C_SCL  [project net LM75_SCL]
PB7/I2C_SDA: R23.1 U4.30(PB7/UART1_RX/I2C_SDA/TIM17_CH1N) ; port PB7/I2C_SDA  [project net LM75_SDA]
PB8: U4.32(PB8/TIM16_CH1) ; port PB8  [project net GPIO13_J5]
PD0/OSC_IN: C11.1 R14.2 U4.2(PD0/OSC_IN) X1.1(X1) ; port PD0/OSC_IN  [also labelled XTAL1]  [project net GPIO15_J5]
PD1/OSC_OUT: R14.1 R17.1 U4.3(PD1/OSC_OUT) ; port PD1/OSC_OUT  [also labelled XTAL2]  [project net GPIO17_J5]
~{RESET}: J2.4 J8.1 U4.4(NRST) ; port ~{RESET}
SWCLK/PA14: J2.3 R12.2 U4.24(PA14/SWCLK/UART2_TX) ; port SWCLK/PA14  [project net IO 2_MicroP]
SWDIO/PA13: J2.2 R11.1 U4.23(PA13/SWDIO) ; port SWDIO/PA13  [project net IO 3_MicroP]
NetC10_1: C10.1 D2.1 J8.2 R10.1 S1.2 S1.3
NetC12_1: C12.1 R17.2 X1.3(X2)

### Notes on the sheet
- (near J17) BOOT0
- 调试
- R1 could be shorted if  pcb space is too small
- (near S1) RST

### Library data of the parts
C10 = 1.02.01.0036: 105,1μF,±10%,16V,X7R,0603,*,RoHS; 名称: 电容; 封装: 0603; 厂商: TDK; 贴片和直插: SMT; 器件优选方案: 正常状态，可以选用; 设备封装名称: C0603_105_X7R_16V_10%
C11 C12 = 1.02.01.0005: 22P,±5%,50V,COG,0603,*,RoHS; 名称: 电容; 封装: 0603; 设备封装名称: C0603_22P_COG_50V_5%; 厂商: muRata; 贴片和直插: SMT; 器件优选方案: 临时/偏门物料/不主推物料，谨慎选用
C26 = 1.02.01.0080: as C6 on sheet 01.Main
C27 = 1.02.01.0032: 104,±10%,50V,X7R,0603,*,RoHS; 名称: 电容; 封装: 0603; 设备封装名称: C0603_104_X7R_50V_10%; 厂商: muRata; 贴片和直插: SMT; 器件优选方案: 量产物料,优先选用
C28 = 1.02.02.0055: as C1 on sheet 02A.Power_CAT6219_Digital
D2 = 1.04.07.0027: as D1 on sheet 03.板载外设 BEEP PNP
J2 = CON5: Connector
J8 J17 = CON2: Connector
R10-R12 R22 R23 R26 = 1.01.01.0052: as R1 on sheet 03.板载外设 BEEP PNP
R14 = 1.01.01.0196: 510KΩ,±1%,0603,RoHS; 名称: 电阻; 封装: 0603; 厂商: Ralec; 贴片和直插: SMT; 器件优选方案: 停产/问题，禁止选用
R17 = 1.01.01.0033: 510Ω,0603,*,RoHS; 名称: 电阻; 封装: 0603; 设备封装名称: R0603_510R; 厂商: Ralec; 贴片和直插: SMT; 器件优选方案: 正常状态，可以选用
R25 = 1.01.01.0007: as R13 on sheet 01.Main
R27 = 1.01.01.0051: 10KΩ,0603,*,RoHS; 名称: 电阻; 封装: 0603; 设备封装名称: R0603_10K; 厂商: Ralec; 贴片和直插: SMT; 器件优选方案: 正常状态，可以选用
S1 = 1.09.01.0003: as S2 on sheet 03.板载外设 BEEP PNP
U4 = 1.05.01.0128: ZLG116N32A,QFN-32,ZLG,RoHs; 名称: 集成电路; 贴片和直插: SMT; PCB备注: 170810CZY; 器件优选方案: 正常状态，可以选用
X1 = 1.07.01.0032: 12.0000MHz,±10ppm,10pF,-40~85℃,±10ppm,SMD3225,*,JYEG,RoHS; 名称: 晶体; 贴片和直插: SMT; PCB备注: 151229lmd; 器件优选方案: 正常状态，可以选用

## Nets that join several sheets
3.3V: 01.Main (R13.2), 02A.Power_CAT6219_Digital (R15.1 R16.2), 05.Miniport_Host (J3.1 J4.1 J5.1), 04.Microport_Host (J27.26), 03.板载外设 BEEP PNP (9 pins), 08.MCU_ZLG116N32A_0603 (12 pins)
3.3VA: 01.Main (C6.2 R13.1), 04.Microport_Host (J35.3)
5V: 02A.Power_CAT6219_Digital (C1.1 C2.1 U1.1 U1.3), 07.USB Device_MicroUSB_CON (J1.1), 05.Miniport_Host (J3.2 J4.2 J5.2), 04.Microport_Host (J35.1), 03.板载外设 BEEP PNP (R7.1)
AGND: 01.Main (C6.1), 02A.Power_CAT6219_Digital (7 pins), 07.USB Device_MicroUSB_CON (5 pins), 05.Miniport_Host (6 pins), 04.Microport_Host (J27.1 J27.18), 03.板载外设 BEEP PNP (10 pins), 08.MCU_ZLG116N32A_0603 (15 pins)
ADC0/IO19_MicroP: 05.Miniport_Host (J3.6 J4.6), 04.Microport_Host (J27.17), 08.MCU_ZLG116N32A_0603 (U4.7)
ADC1/IO20_MicroP: 05.Miniport_Host (J3.5 J4.5), 04.Microport_Host (J27.16), 08.MCU_ZLG116N32A_0603 (U4.6)
CS/GPIO7_Minip: 05.Miniport_Host (J3.7 J4.7), 04.Microport_Host (J27.22), 08.MCU_ZLG116N32A_0603 (U4.10)
CTS/IO13_MicroP: 05.Miniport_Host (J3.14 J4.14), 04.Microport_Host (J27.6), 08.MCU_ZLG116N32A_0603 (U4.22)
DAC/IO21_MicroP: 05.Miniport_Host (J3.20 J4.20), 04.Microport_Host (J27.15), 08.MCU_ZLG116N32A_0603 (U4.28)
GPIO5_J5: 05.Miniport_Host (J5.5), 03.板载外设 BEEP PNP (J14.1 R8.1), 08.MCU_ZLG116N32A_0603 (U4.18)
GPIO7_J5: 05.Miniport_Host (J5.7), 03.板载外设 BEEP PNP (J6.1), 08.MCU_ZLG116N32A_0603 (U4.14)
GPIO8_Minip: 05.Miniport_Host (J3.8 J4.8), 04.Microport_Host (J27.5), 08.MCU_ZLG116N32A_0603 (U4.25)
GPIO9_J5: 05.Miniport_Host (J5.9), 03.板载外设 BEEP PNP (J9.1), 08.MCU_ZLG116N32A_0603 (U4.15)
GPIO10_J5: 05.Miniport_Host (J5.10), 04.Microport_Host (J27.9), 08.MCU_ZLG116N32A_0603 (U4.20)
GPIO11_J5: 05.Miniport_Host (J5.11), 03.板载外设 BEEP PNP (J10.1), 08.MCU_ZLG116N32A_0603 (U4.16)
GPIO11_Minip: 05.Miniport_Host (J3.11 J4.11), 04.Microport_Host (J27.7), 08.MCU_ZLG116N32A_0603 (U4.21)
GPIO12_J5: 05.Miniport_Host (J5.12), 04.Microport_Host (J27.8), 08.MCU_ZLG116N32A_0603 (U4.19)
GPIO13_J5: 05.Miniport_Host (J5.13), 04.Microport_Host (J27.4), 03.板载外设 BEEP PNP (J7.1), 08.MCU_ZLG116N32A_0603 (U4.32)
GPIO15_J5: 05.Miniport_Host (J5.15), 08.MCU_ZLG116N32A_0603 (C11.1 R14.2 U4.2 X1.1)
GPIO16_Minip: 05.Miniport_Host (J3.16 J4.16), 04.Microport_Host (J27.3), 08.MCU_ZLG116N32A_0603 (U4.26)
GPIO17_J5: 05.Miniport_Host (J5.17), 08.MCU_ZLG116N32A_0603 (R14.1 R17.1 U4.3)
GPIO18_Minip: 05.Miniport_Host (J3.18 J4.18), 04.Microport_Host (J27.14), 08.MCU_ZLG116N32A_0603 (U4.27)
IO 1_MicroP: 05.Miniport_Host (J3.12 J4.12), 04.Microport_Host (J27.23), 08.MCU_ZLG116N32A_0603 (U4.8)
IO 2_MicroP: 04.Microport_Host (J27.11), 08.MCU_ZLG116N32A_0603 (J2.3 R12.2 U4.24)
IO 3_MicroP: 04.Microport_Host (J27.10), 08.MCU_ZLG116N32A_0603 (J2.2 R11.1 U4.23)
LM75_SCL: 05.Miniport_Host (J3.17 J4.17), 04.Microport_Host (J27.12), 03.板载外设 BEEP PNP (J11.1), 08.MCU_ZLG116N32A_0603 (R22.1 U4.29)
LM75_SDA: 05.Miniport_Host (J3.19 J4.19), 04.Microport_Host (J27.13), 03.板载外设 BEEP PNP (J13.1), 08.MCU_ZLG116N32A_0603 (R23.1 U4.30)
MISO/GPIO9_Minip: 05.Miniport_Host (J3.9 J4.9), 04.Microport_Host (J27.20), 08.MCU_ZLG116N32A_0603 (U4.12)
MOSI/GPIO15_Minip: 05.Miniport_Host (J3.15 J4.15), 04.Microport_Host (J27.21), 08.MCU_ZLG116N32A_0603 (U4.13)
PA3/UART2_RX: 05.Miniport_Host (J3.10 J4.10), 04.Microport_Host (J27.24), 08.MCU_ZLG116N32A_0603 (U4.9)
PA5/SPI1_SCK: 05.Miniport_Host (J3.13 J4.13), 04.Microport_Host (J27.19), 08.MCU_ZLG116N32A_0603 (U4.11)
~{RESET}: 04.Microport_Host (J27.2), 08.MCU_ZLG116N32A_0603 (J2.4 J8.1 U4.4)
